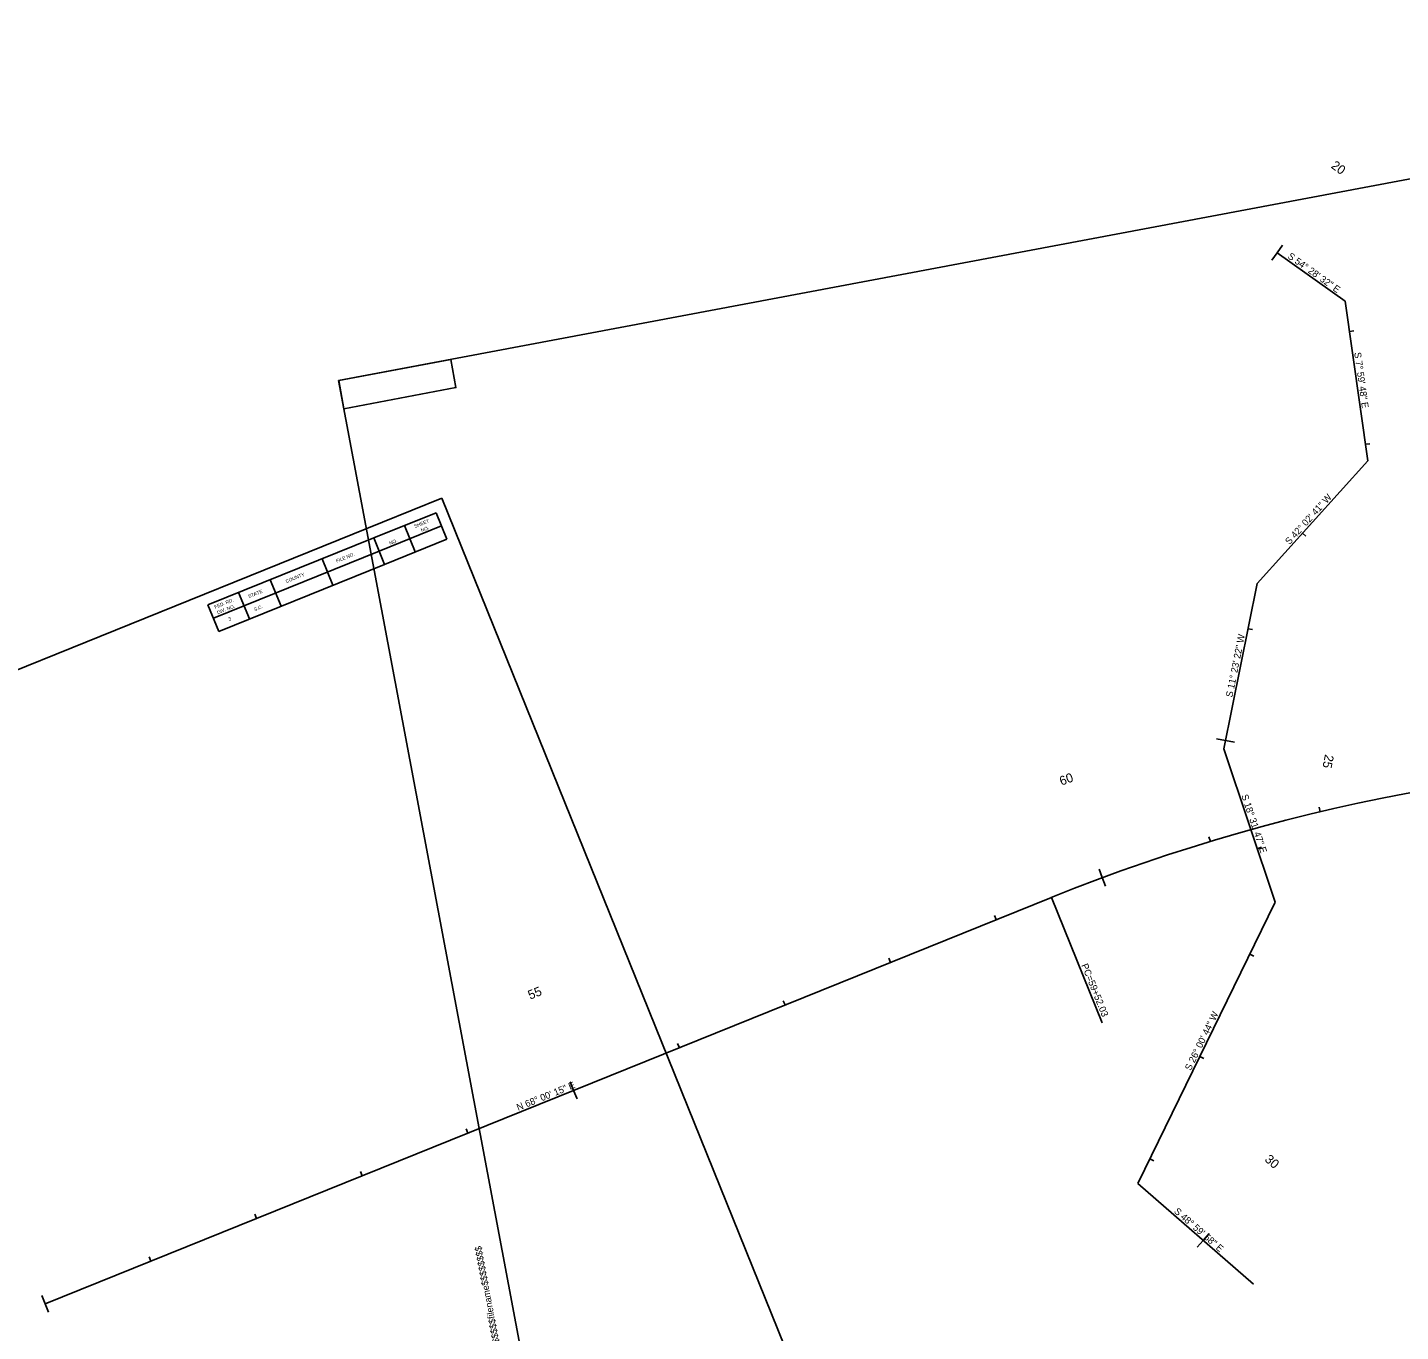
# Model space of a CAD drawing. Extents: x 1965566 to 1970293, y 1116554 to 1118568.
# Drawn here: x 1966755 to 1967960, y 1117424 to 1118568 of the extents above; entities that cross this region are included whole.
import ezdxf

# ---------------------------------------------------------------- set-up
doc = ezdxf.new("R2010")
doc.units = 0
for name, color, linetype in [('Level 1', 7, 'Continuous'), ('Level 21', 7, 'Continuous'), ('Level 35', 7, 'Continuous')]:
    doc.layers.add(name, color=color, linetype=linetype)

msp = doc.modelspace()

# ---------------------------------------------------------------- linework, layer by layer
at = {"layer": 'Level 1'}
for p, q in [((1968674.2, 1118567.8), (1967028.1, 1118258)), ((1967851.7, 1118370.2), (1967856.4, 1118376.7)), ((1967851.7, 1118370.2), (1967847.1, 1118363.7)), ((1967851.7, 1118370.2), (1967911.4, 1118327.7)), ((1967851.7, 1118370.2), (1967911.4, 1118327.7)), ((1967911.4, 1118327.7), (1967931.1, 1118187.5)), ((1967911.4, 1118327.7), (1967931.1, 1118187.5)), ((1967915.1, 1118301.2), (1967919, 1118301.7)), ((1967028.1, 1118258), (1967222.3, 1117226.1)), ((1967929, 1118202.2), (1967933, 1118202.7)), ((1967931.1, 1118187.5), (1967834, 1118080)), ((1967931.1, 1118187.5), (1967834, 1118080)), ((1967118.8, 1118154.9), (1965565.8, 1117527.6)), ((1967512.1, 1117181.4), (1967118.8, 1118154.9)), ((1967059.1, 1118120), (1967113.8, 1118142.1)), ((1967086, 1118130.9), (1967095.3, 1118107.7)), ((1967113.8, 1118142.1), (1967123.1, 1118118.9)), ((1966913.5, 1118061.2), (1967059.1, 1118120)), ((1967059.1, 1118120), (1967068.4, 1118096.8)), ((1967063.8, 1118108.4), (1967118.5, 1118130.5)), ((1967068.4, 1118096.8), (1967123.1, 1118118.9)), ((1967874, 1118124.2), (1967876.9, 1118121.6)), ((1966918.2, 1118049.6), (1967063.8, 1118108.4)), ((1966922.9, 1118038), (1967068.4, 1118096.8)), ((1967013.6, 1118101.7), (1967023, 1118078.5)), ((1966968.2, 1118083.3), (1966977.6, 1118060.1)), ((1966940.4, 1118072.1), (1966949.8, 1118048.9)), ((1967834, 1118080), (1967804.8, 1117934.9)), ((1967834, 1118080), (1967804.8, 1117934.9)), ((1966913.5, 1118061.2), (1966922.9, 1118038)), ((1967826.1, 1118040.4), (1967830, 1118039.6)), ((1967806.3, 1117942.4), (1967798.5, 1117943.9)), ((1967806.3, 1117942.4), (1967814.2, 1117940.8)), ((1967804.8, 1117934.9), (1967849.8, 1117800.6)), ((1967804.8, 1117934.9), (1967849.8, 1117800.6)), ((1967889.5, 1117879.8), (1967888.6, 1117883.7)), ((1967793, 1117853.8), (1967791.8, 1117857.7)), ((1967834.2, 1117847.3), (1967838, 1117848.6)), ((1967698.2, 1117822), (1967695.4, 1117829.5)), ((1967698.2, 1117822), (1967701, 1117814.5)), ((1966770.7, 1117448.1), (1967653.5, 1117804.7)), ((1967653.5, 1117804.7), (1967698, 1117694.6)), ((1967849.8, 1117800.6), (1967729.3, 1117553.7)), ((1967849.8, 1117800.6), (1967729.3, 1117553.7)), ((1967605.2, 1117785.2), (1967603.7, 1117788.9)), ((1967512.5, 1117747.7), (1967511, 1117751.5)), ((1967827.6, 1117755), (1967831.1, 1117753.2)), ((1967419.8, 1117710.3), (1967418.3, 1117714)), ((1967327.1, 1117672.8), (1967325.6, 1117676.5)), ((1967783.7, 1117665.1), (1967787.3, 1117663.4)), ((1967234.3, 1117635.4), (1967231.3, 1117642.8)), ((1967234.3, 1117635.4), (1967237.3, 1117628)), ((1967141.6, 1117597.9), (1967140.1, 1117601.6)), ((1967739.8, 1117575.2), (1967743.4, 1117573.5)), ((1967048.9, 1117560.5), (1967047.4, 1117564.2)), ((1967729.3, 1117553.7), (1967830.8, 1117465.4)), ((1967729.3, 1117553.7), (1967830.8, 1117465.4)), ((1966956.2, 1117523), (1966954.7, 1117526.7)), ((1967786.6, 1117503.8), (1967791.9, 1117509.8)), ((1967786.6, 1117503.8), (1967781.4, 1117497.8)), ((1966863.5, 1117485.6), (1966862, 1117489.3)), ((1966770.7, 1117448.1), (1966767.7, 1117455.5)), ((1966770.7, 1117448.1), (1966773.7, 1117440.7))]:
    msp.add_line(p, q, dxfattribs=at)
msp.add_lwpolyline([(1967032.8, 1118233.4), (1967028.2, 1118258), (1967126.5, 1118276.5), (1967131.1, 1118251.9)], close=True, dxfattribs=at)
msp.add_arc((1968266.6, 1116286.8), 1637, 87.7266, 111.9958, dxfattribs=at)
at = {"layer": 'Level 35'}
msp.add_line((1967226.5, 1117632.2), (1967226.5, 1117632.2), dxfattribs=at)

# ---------------------------------------------------------------- texts
at = {"layer": 'Level 1'}
for s, height, rotation, p in [('SHEET', 3, 21.9958, (1967095.1, 1118128.6)), ('NO.', 3, 21.9958, (1967101, 1118125.1)), ('FILE NO.', 3, 21.9958, (1967026.5, 1118098.2)), ('NO.', 3, 21.9958, (1967073.2, 1118113.8)), ('COUNTY', 3, 21.9958, (1966982.3, 1118080.4)), ('STATE', 3, 21.9958, (1966949.4, 1118067.1)), ('FED. RD.', 3, 21.9958, (1966919.8, 1118057.8)), ('DIV. NO.', 3, 21.9958, (1966922.2, 1118052.9)), ('S.C.', 3, 21.9958, (1966954.4, 1118055.6)), ('3', 3, 21.9958, (1966932.1, 1118047.2)), ('PC=59+52.03', 6, 291.9958, (1967679.7, 1117745.2)), ('$$$$$$path$$$$$$$$filename$$$$$$$$', 5.88, 100.6591, (1967179.3, 1117360.4))]:
    msp.add_text(s, height=height, rotation=rotation, dxfattribs=at).set_placement(p)
at = {"layer": 'Level 21'}
for s, height, rotation, p in [('20', 8, 324.4755, (1967898.3, 1118445.1)), ('S 54%%d 28\' 32" E', 6, 324.4755, (1967860.3, 1118365.9)), ('S 7%%d 59\' 48" E', 6, 277.9968, (1967919.2, 1118282.5)), ('S 42%%d 02\' 41" W', 6, 47.9551, (1967862.4, 1118113.6)), ('S 11%%d 23\' 22" W', 6, 78.6104, (1967812.3, 1117979.8)), ('25', 8, 258.6104, (1967893.7, 1117930.5)), ('60', 8, 20.3171, (1967662.4, 1117902.6)), ('S 18%%d 31\' 47" E', 6, 288.5298, (1967820.1, 1117894)), ('55', 8, 21.9958, (1967196.2, 1117714.9)), ('S 26%%d 00\' 44" W', 6, 63.9877, (1967775.7, 1117652.2)), ('N 68%%d 00\' 15" E', 6, 21.9958, (1967185.7, 1117617.4)), ('30', 8, 318.9993, (1967840.1, 1117573.9)), ('S 48%%d 59\' 58" E', 6, 318.9993, (1967760.6, 1117528.5))]:
    msp.add_text(s, height=height, rotation=rotation, dxfattribs=at).set_placement(p)

doc.saveas('drawing.dxf')
